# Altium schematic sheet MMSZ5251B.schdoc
size 127 x 101 mm
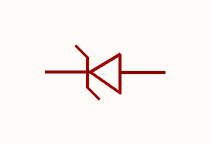
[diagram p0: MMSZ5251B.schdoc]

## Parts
ZD?  mmsz5251b  [SOD-123_L2.8-W1.8-LS3.7-RD]  (value not drawn)

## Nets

Not connected (* = marked no-connect by the designer): ZD? 1(K) 2(A)

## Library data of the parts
ZD? = mmsz5251b: 二极管配置:1个独立式;稳压值(标称值):22V;稳压值(范围):20.9V~23.1V;耗散功率(Pd):350mW;; Manufacturer: CJ(江苏长电/长晶); AddInBom: yes; ModelId: 7884390a25fb4c08947731ebfba7e3f8; ModelTransform: 144.8816,62.992,0,0,0,0,0,0,0; Diode Configuration: 1个独立式; Zener Voltage(Nom): 22V; Reverse Leakage Current (Ir): 100nA; Pd - Power Dissipation: 350mW; Impedance(Zzt): 29Ω; Impedance(Zzk): 600Ω; Operating Junction Temperature Range: -65℃~+150℃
